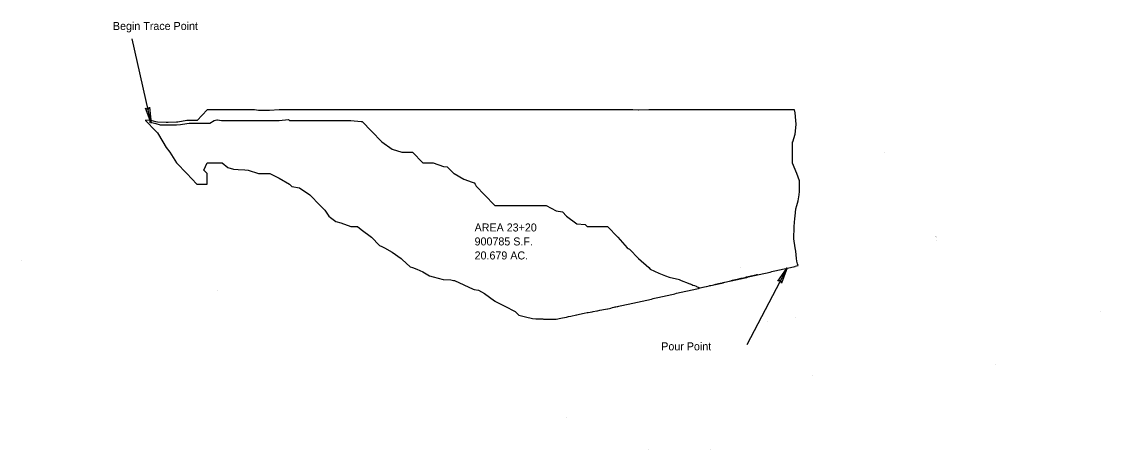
# Model space of a CAD drawing. Extents: x 2588 to 5959, y 2700 to 4038.
import ezdxf

# ---------------------------------------------------------------- set-up
doc = ezdxf.new("R2010")
doc.units = 0
for name, color, linetype in [('Default', 7, 'Continuous'), ('DESIGN - SCRATCH - User 1', 7, 'Continuous'), ('SURVEY - CENTERLINE - Preliminary', 7, 'Continuous'), ('SURVEY - CENTERLINE - Preliminary Text', 7, 'Continuous')]:
    doc.layers.add(name, color=color, linetype=linetype)

msp = doc.modelspace()

# ---------------------------------------------------------------- linework, layer by layer
at = {"layer": 'DESIGN - SCRATCH - User 1'}
msp.add_line((4980.4, 3267.8), (4854.3, 3027.7), dxfattribs=at)
msp.add_lwpolyline([(4980.4, 3267.8), (4962.6, 3220.4), (4960.1, 3229.1), (4951.3, 3226.4)], close=True, dxfattribs=at)
msp.add_lwpolyline([(4980.4, 3267.8), (4962.6, 3220.4), (4960.1, 3229.1), (4951.3, 3226.4), (4980.4, 3267.8)], dxfattribs=at)
at = {"layer": 'SURVEY - CENTERLINE - Preliminary'}
for p, q in [((5285.3, 3629.3), (5285.3, 3629.3)), ((5285.3, 3629.3), (5285.3, 3629.3)), ((5285.3, 3629.3), (5285.3, 3629.3)), ((5445.1, 3366.8), (5445.1, 3366.8)), ((5445.1, 3366.8), (5445.1, 3366.8)), ((5445.1, 3366.8), (5445.1, 3366.8)), ((5445.1, 3366.8), (5445.1, 3366.8)), ((5445.1, 3366.5), (5445.1, 3366.5)), ((5445.1, 3366.5), (5445.1, 3366.5)), ((5445.1, 3366.5), (5445.1, 3366.5)), ((5445.1, 3366.5), (5445.1, 3366.5)), ((5445.5, 3365.1), (5445.5, 3365.1)), ((5445.5, 3365.1), (5445.5, 3365.1)), ((5445.5, 3365.1), (5445.5, 3365.1)), ((5445.5, 3365.1), (5445.5, 3365.1)), ((5445.7, 3364), (5445.7, 3364)), ((5445.7, 3364), (5445.7, 3364)), ((5445.7, 3364), (5445.7, 3364)), ((5445.7, 3364), (5445.7, 3364)), ((5445.8, 3363.7), (5445.8, 3363.7)), ((5445.8, 3363.7), (5445.8, 3363.7)), ((5445.8, 3363.7), (5445.8, 3363.7)), ((5445.8, 3363.7), (5445.8, 3363.7)), ((5448.2, 3353.2), (5448.2, 3353.2)), ((5448.2, 3353.2), (5448.2, 3353.2)), ((2588.2, 3291.4), (2588.2, 3291.4)), ((2588.2, 3291.4), (2588.2, 3291.4)), ((2588.2, 3291.4), (2588.2, 3291.4)), ((2588.2, 3291.4), (2588.2, 3291.4)), ((4833.9, 3267.8), (4833.9, 3267.8)), ((4887.7, 3247.2), (4887.7, 3247.2)), ((4887.7, 3247.2), (4887.7, 3247.2)), ((4887.7, 3247.2), (4887.7, 3247.2)), ((4887.7, 3247.2), (4887.7, 3247.2)), ((4980.4, 3267.8), (4980.4, 3267.8)), ((4980.4, 3267.8), (4980.4, 3267.8)), ((4980.4, 3267.8), (4980.4, 3267.8)), ((4980.4, 3267.8), (4980.4, 3267.8)), ((3200.3, 3197.8), (3200.3, 3197.8)), ((3200.3, 3197.8), (3200.3, 3197.8)), ((3200.3, 3197.8), (3200.3, 3197.8)), ((3200.3, 3197.8), (3200.3, 3197.8)), ((5005.2, 3111.9), (5005.2, 3111.9)), ((5005.2, 3111.9), (5005.2, 3111.9)), ((5005.2, 3111.9), (5005.2, 3111.9)), ((5958.9, 3131.4), (5958.9, 3131.4)), ((5958.9, 3131.4), (5958.9, 3131.4)), ((5958.9, 3131.4), (5958.9, 3131.4)), ((5958.9, 3131.4), (5958.9, 3131.4)), ((4920.1, 3100.2), (4920.1, 3100.2)), ((4920.1, 3100.2), (4920.1, 3100.2)), ((4920.1, 3100.2), (4920.1, 3100.2)), ((5631.4, 2965.6), (5631.4, 2965.6)), ((5631.4, 2965.6), (5631.4, 2965.6)), ((5631.4, 2965.6), (5631.4, 2965.6)), ((5631.4, 2965.6), (5631.4, 2965.6)), ((5060.8, 2932.3), (5060.8, 2932.3)), ((5060.8, 2932.3), (5060.8, 2932.3)), ((5060.8, 2932.3), (5060.8, 2932.3)), ((5060.8, 2932.3), (5060.8, 2932.3)), ((4290.9, 2799.6), (4290.9, 2799.6)), ((4290.9, 2799.6), (4290.9, 2799.6)), ((4290.9, 2799.6), (4290.9, 2799.6)), ((4290.9, 2799.6), (4290.9, 2799.6)), ((4547.5, 2700), (4547.5, 2700)), ((4547.5, 2700), (4547.5, 2700)), ((4547.5, 2700), (4547.5, 2700)), ((4547.5, 2700), (4547.5, 2700)), ((4740, 2700), (4740, 2700)), ((4740, 2700), (4740, 2700)), ((4740, 2700), (4740, 2700)), ((4740, 2700), (4740, 2700))]:
    msp.add_line(p, q, dxfattribs=at)
for points in [[(5014.7, 3275), (5013, 3280.4), (5010.5, 3288.6), (5010.3, 3289.2), (5009.3, 3297.4), (5006.9, 3319.9), (5004.9, 3330.6), (5001.4, 3358.8), (5001.5, 3363.8), (5002, 3391.4), (5002.3, 3396.9), (5004, 3422.5), (5004.7, 3430.1), (5006.8, 3452.8), (5010.2, 3463.3), (5014.9, 3477.6), (5017.8, 3496.5), (5019, 3506.6), (5018.5, 3529.7), (5018.4, 3540.4), (5010.4, 3562.9), (4996.6, 3595.7), (4996.6, 3596.1), (4997.2, 3628.7), (4997.2, 3629.3), (4997.3, 3661.7), (4997.4, 3662.4), (5005.7, 3686.2), (5006.6, 3695.6), (5008, 3717), (5006.8, 3728.8), (5005.4, 3752.9), (5003.1, 3762), (4996.6, 3762), (4964.5, 3762), (4932.5, 3762), (4900.4, 3762), (4868.3, 3762), (4836.2, 3762), (4804.2, 3762), (4772.1, 3762), (4740, 3762), (4707.9, 3762), (4675.9, 3762), (4643.8, 3762), (4611.7, 3762), (4579.6, 3762), (4547.5, 3762), (4516.3, 3761.1), (4515.5, 3761.2), (4498.1, 3762), (4483.4, 3762), (4451.3, 3762), (4419.2, 3762), (4387.2, 3762), (4355.1, 3762), (4323, 3762), (4290.9, 3762), (4258.9, 3762), (4226.8, 3762), (4194.7, 3762), (4162.6, 3762), (4130.5, 3762), (4098.5, 3762), (4066.4, 3762), (4034.3, 3762), (4002.2, 3762), (3970.2, 3762), (3938.1, 3762), (3906, 3762), (3873.9, 3762), (3841.9, 3762), (3809.8, 3762), (3777.7, 3762), (3745.6, 3762), (3713.5, 3762), (3681.5, 3762), (3649.4, 3762), (3617.3, 3762), (3585.2, 3762), (3553.2, 3762), (3521.1, 3762), (3489, 3762), (3456.9, 3762), (3424.9, 3762), (3392.8, 3762), (3362.9, 3759.8), (3360.7, 3759.8), (3330.4, 3760.2), (3328.6, 3760.5), (3315.5, 3762), (3296.5, 3762), (3264.5, 3762), (3232.4, 3762), (3200.3, 3762), (3168.2, 3762), (3152.3, 3745.3), (3136.5, 3728.8), (3136.2, 3728.8), (3104.2, 3728.7), (3104.1, 3728.7), (3076.8, 3723.8), (3072, 3723.7), (3045.8, 3722.8), (3039.9, 3722.8), (3013.3, 3723.2), (3007.9, 3725), (2992.6, 3728.8), (2975.8, 3729.7), (2974.9, 3729.7), (2975.8, 3728.8)], [(2975.8, 3728.8), (3007.9, 3695.6), (3012.9, 3690.4), (3029.9, 3662.4), (3039.9, 3644.9), (3051.9, 3629.3), (3072, 3596.1), (3104.1, 3562.9), (3136.2, 3529.7), (3168.2, 3529.7), (3168.2, 3562.9), (3157.7, 3573.8), (3168.2, 3596.1), (3200.3, 3596.1), (3214.6, 3596.1), (3232.4, 3581.8), (3250.7, 3577.1), (3264.5, 3575.8), (3285.5, 3574.3), (3296.5, 3573.1), (3328.6, 3562.9), (3360.7, 3562.9), (3363.7, 3562.9), (3392.8, 3548.8), (3424.9, 3529.7), (3432.3, 3522), (3456.9, 3518.3), (3489, 3496.5), (3521.1, 3463.3), (3535.4, 3448.6), (3548.6, 3430.1), (3553.2, 3425.1), (3569.9, 3412.8), (3585.2, 3408.5), (3617.3, 3396.9), (3637.5, 3396.9), (3649.4, 3388.4), (3681.5, 3363.8), (3706.5, 3337.8), (3713.5, 3334.9), (3722.6, 3330.6), (3745.6, 3316.8), (3774.2, 3297.4), (3777.7, 3294.4), (3802.7, 3271.5), (3809.8, 3269.2), (3823.4, 3264.2), (3841.9, 3255.2), (3862.3, 3243.1), (3873.9, 3240.4), (3905, 3232), (3906, 3232), (3929, 3231), (3938.1, 3228.6), (3940.9, 3228), (3970.2, 3214.5)], [(2986.7, 3725.1), (3007.9, 3719.9), (3020.8, 3715.4), (3039.9, 3715.2), (3053.3, 3715), (3072, 3715.7), (3084.4, 3716), (3104.1, 3719.5), (3112, 3720.6), (3136.2, 3720.7), (3144, 3720.8), (3168.2, 3720.5), (3176.4, 3720.4), (3190.2, 3728.8), (3198.1, 3731.1), (3200.3, 3730.8), (3213.1, 3728.8), (3232.4, 3728.8), (3264.5, 3728.8), (3296.5, 3728.8), (3328.6, 3728.8), (3360.7, 3728.8), (3392.8, 3728.8), (3422.3, 3731.5), (3424.9, 3729), (3425.4, 3728.8), (3456.9, 3728.8), (3489, 3728.8), (3521.1, 3728.8), (3553.2, 3728.8), (3585.2, 3728.8), (3617.3, 3728.8), (3649.4, 3725.7), (3652.8, 3725.3), (3681.5, 3695.6), (3713.5, 3662.4), (3745.6, 3639.3), (3776.5, 3629.3), (3777.7, 3629.3), (3809.8, 3629.3), (3841.9, 3596.1), (3873.9, 3596.1), (3906, 3585.2), (3918, 3583.7), (3938.1, 3563.9), (3939.8, 3562.9), (3970.2, 3545.8), (3996.4, 3535.7), (4002.2, 3533.7), (4005.4, 3529.7), (4008.3, 3523.4), (4034.3, 3496.5), (4066.4, 3463.3), (4098.5, 3463.3), (4130.5, 3463.3), (4162.6, 3463.3), (4194.7, 3463.3), (4226.8, 3463.3), (4258.9, 3446.8), (4278.3, 3443.2), (4290.9, 3430.1), (4323, 3406.1), (4348.9, 3403.3), (4355.1, 3396.9), (4419.2, 3396.9), (4451.3, 3363.8), (4480.7, 3330.6), (4483.4, 3328.6), (4487.5, 3326.3), (4515.5, 3297.4), (4547.5, 3268.8), (4552.1, 3264.2), (4579.6, 3251), (4600.5, 3242.6), (4611.7, 3239.3), (4643.6, 3231.2), (4643.8, 3231.1), (4644, 3231), (4675.9, 3218.3), (4676.8, 3217.9), (4679.1, 3216.9), (4682, 3215.8), (4685.7, 3214.3), (4690.6, 3212.4), (4695.9, 3210.2), (4697.3, 3209.7), (4698.7, 3209.1), (4707.1, 3205.8), (4707.5, 3205.6), (4707.7, 3205.5), (4707.9, 3205.6), (4712.4, 3206.6), (4712.5, 3206.6), (4717.2, 3207.6), (4722.1, 3208.7), (4727, 3209.8), (4728.2, 3210.1), (4731.9, 3210.9), (4732.5, 3211), (4736.8, 3212), (4738.5, 3212.4), (4740, 3212.7), (4741.6, 3213.1), (4746.5, 3214.2), (4751.4, 3215.3), (4754.5, 3216), (4756.3, 3216.4), (4756.8, 3216.5), (4761.1, 3217.5), (4761.9, 3217.7), (4765.9, 3218.6), (4766, 3218.6), (4766.8, 3218.8), (4771, 3219.8), (4772.1, 3220), (4778, 3221.4), (4780.7, 3222.1), (4781.1, 3222.2), (4781.2, 3222.2), (4798.6, 3226.3), (4804.2, 3227.7), (4806.5, 3228.2), (4806.8, 3228.3), (4809.8, 3229), (4813.9, 3230), (4814.7, 3230.2), (4818, 3231), (4819.5, 3231.4), (4823.7, 3232.4), (4824.4, 3232.5), (4829.3, 3233.7), (4832.8, 3234.5), (4834.1, 3234.8), (4836.2, 3235.3), (4839, 3236), (4843.9, 3237.1), (4847.6, 3238), (4848.7, 3238.3), (4853.6, 3239.4), (4855.1, 3239.8), (4857.5, 3240.3), (4859, 3240.7), (4860.7, 3241.1), (4861.7, 3241.3), (4868.2, 3242.8), (4868.3, 3242.9), (4876.6, 3244.7), (4877.9, 3245), (4880.4, 3245.6), (4883.8, 3246.3), (4885.3, 3246.7), (4887.4, 3247.1), (4887.7, 3247.2)], [(3970.2, 3214.5), (3999.2, 3201), (4002.2, 3200.3), (4016.3, 3197.8), (4034.3, 3187.6), (4066.3, 3164.6), (4066.4, 3164.6), (4066.8, 3164.2), (4098.5, 3148.3), (4130, 3131.4), (4130.5, 3131), (4142.1, 3119.5), (4162.6, 3115), (4184.2, 3109.1), (4194.7, 3109), (4215.1, 3108.8), (4217.2, 3108.1), (4218.4, 3107.8), (4226.8, 3107.7), (4245.9, 3107.6), (4249.8, 3107.6), (4258, 3107.6), (4258.9, 3107.8), (4272.8, 3110.3), (4278.2, 3111.4), (4290.9, 3114.2), (4297.2, 3115.6), (4304.7, 3117.2), (4321.6, 3120.9), (4323, 3121.2), (4331.2, 3123), (4346, 3126.2), (4355.1, 3127.9), (4358, 3128.4), (4370.7, 3130.7), (4374.4, 3131.4), (4385.2, 3133.5), (4387.2, 3133.9), (4395.2, 3135.4), (4412.2, 3138.7), (4419.2, 3140), (4419.2, 3140.1), (4419.2, 3140.1), (4419.8, 3140.2), (4419.8, 3140.2), (4424.7, 3141.3), (4429.5, 3142.4), (4434.4, 3143.5), (4438.7, 3144.5), (4439.3, 3144.6), (4443.3, 3145.6), (4444.2, 3145.8), (4444.8, 3145.9), (4449.1, 3146.8), (4451.3, 3147.2), (4454, 3147.8), (4458.9, 3148.8), (4463.7, 3149.8), (4468.6, 3150.9), (4473.5, 3151.9), (4483.3, 3153.9), (4488.2, 3155), (4493.1, 3156.1), (4498, 3157.2), (4502.8, 3158.3), (4507.7, 3159.4), (4512.6, 3160.5), (4517.5, 3161.7), (4522.3, 3162.8), (4527.2, 3163.9), (4532.1, 3165), (4537, 3166.1), (4541.8, 3167.2), (4546.7, 3168.3), (4551.6, 3169.4), (4556.5, 3170.5), (4561.3, 3171.7), (4566.2, 3172.8), (4571.1, 3173.9), (4576, 3175), (4580.8, 3176.1), (4585.7, 3177.2), (4590.6, 3178.3), (4595.5, 3179.4), (4600.3, 3180.5), (4605.2, 3181.7), (4610.1, 3182.8), (4615, 3183.9), (4619.8, 3185), (4624.7, 3186.1), (4629.6, 3187.2), (4634.5, 3188.3), (4639.3, 3189.4), (4644.2, 3190.5), (4649.1, 3191.6), (4654, 3192.8), (4658.8, 3193.9), (4663.7, 3195), (4668.6, 3196.1), (4673.5, 3197.2), (4678.3, 3198.3), (4683.2, 3199.4), (4688.1, 3200.5), (4693, 3201.6), (4697.8, 3202.8), (4702.7, 3203.9), (4707.6, 3205), (4712.5, 3206.1), (4717.3, 3207.2), (4722.2, 3208.3), (4727.1, 3209.4), (4732, 3210.5), (4736.8, 3211.6), (4741.7, 3212.7), (4746.6, 3213.9), (4751.5, 3215), (4756.3, 3216.1), (4761.2, 3217.2), (4766.1, 3218.3), (4771, 3219.4), (4775.8, 3220.5), (4780.7, 3221.6), (4785.6, 3222.7), (4790.5, 3223.9), (4795.3, 3225), (4800.2, 3226.1), (4805.1, 3227.2), (4810, 3228.3), (4814.8, 3229.4), (4819.7, 3230.5), (4824.6, 3231.6), (4829.5, 3232.7), (4834.3, 3233.8), (4839.2, 3235), (4844.1, 3236.1), (4849, 3237.2), (4853.8, 3238.3), (4858.7, 3239.4), (4863.6, 3240.5), (4868.5, 3241.6), (4873.3, 3242.7), (4878.2, 3243.8), (4883.1, 3245), (4888, 3246.1), (4892.8, 3247.2), (4897.7, 3248.3), (4902.6, 3249.4), (4907.5, 3250.5), (4912.3, 3251.6), (4917.2, 3252.7), (4922.1, 3253.8), (4927, 3254.9), (4931.8, 3256.1), (4936.7, 3257.2), (4941.6, 3258.3), (4946.5, 3259.4), (4951.3, 3260.5), (4956.2, 3261.6), (4961.1, 3262.7), (4966, 3263.8), (4970.8, 3264.9), (4975.7, 3266.1), (4980.6, 3267.2), (4985.5, 3268.3), (4990.3, 3269.4), (4995.2, 3270.5), (5000.1, 3271.6), (5005, 3272.7), (5004.9, 3272.9), (5009.8, 3274), (5014.7, 3275)]]:
    msp.add_lwpolyline(points, dxfattribs=at)
at = {"layer": 'SURVEY - CENTERLINE - Preliminary Text'}
msp.add_line((2992.9, 3720.1), (2933.3, 3984.7), dxfattribs=at)
msp.add_lwpolyline([(2992.9, 3720.1), (2975.8, 3767.8), (2983.3, 3762.8), (2988.2, 3770.6)], close=True, dxfattribs=at)
msp.add_lwpolyline([(2992.9, 3720.1), (2975.8, 3767.8), (2983.3, 3762.8), (2988.2, 3770.6), (2992.9, 3720.1)], dxfattribs=at)

# ---------------------------------------------------------------- texts
at = {"layer": 'Default'}
for s, p in [('AREA 23+20', (4003.6, 3381.8)), ('900785 S.F.', (4003.6, 3338.1)), ('20.679 AC.', (4003.6, 3294.3))]:
    msp.add_text(s, height=25, dxfattribs=at).set_placement(p)
at = {"layer": 'DESIGN - SCRATCH - User 1'}
msp.add_text('Pour Point', height=25, dxfattribs=at).set_placement((4586.8, 3010))
at = {"layer": 'SURVEY - CENTERLINE - Preliminary Text'}
msp.add_text('Begin Trace Point', height=25, dxfattribs=at).set_placement((2873.6, 4012))

doc.saveas('drawing.dxf')
